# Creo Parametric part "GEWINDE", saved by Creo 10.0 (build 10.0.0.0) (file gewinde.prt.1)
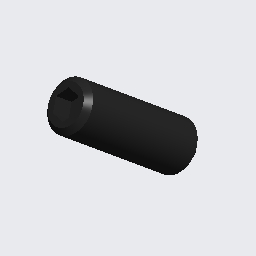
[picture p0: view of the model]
Units: millimeter Newton Second (mmNs); MM, TONNE, SECS

Created from: 61900412.PRT

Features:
  1. coordinate system "61900412"
  2. imported feature "Import-ke ID 5"

Other named items: NOTE_0

Notes: 61900412

Surfaces: 9 plane, 4 cone, 2 cylinder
